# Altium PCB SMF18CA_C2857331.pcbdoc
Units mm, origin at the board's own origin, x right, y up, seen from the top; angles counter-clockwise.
Board outline 17.27 x 14.65 mm, 2 copper layers (Top Layer, Bottom Layer), stack 0 mm thick; 1 components, 0 nets, 2 pads, 0 vias.
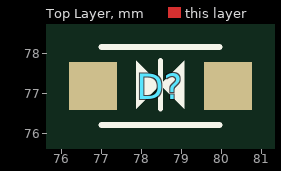
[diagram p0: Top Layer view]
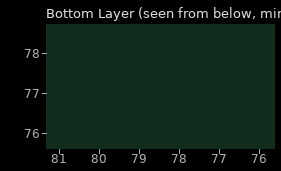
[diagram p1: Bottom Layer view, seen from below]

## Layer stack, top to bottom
Top Layer: signal copper (thickness not stored)
Bottom Layer: signal copper (thickness not stored)

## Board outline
87.12,69.85 69.85,69.85 69.85,84.502 87.12,84.502

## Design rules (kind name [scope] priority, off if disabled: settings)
PasteMaskExpansion "Paste Mask Expansion" [All] p1: expansion=0
SolderMaskExpansion "Solder Mask Expansion" [IsVia] p1: expansion=-25.4 istentingtop=TRUE
SolderMaskExpansion "Solder Mask Expansion" [All] p2: expansion=0.051 istentingtop=FALSE

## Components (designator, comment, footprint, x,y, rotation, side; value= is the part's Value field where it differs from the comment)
D? "SMF18CA" SMF_L2.8-W1.8-LS3.7-BI 78.485,77.176 r0 top

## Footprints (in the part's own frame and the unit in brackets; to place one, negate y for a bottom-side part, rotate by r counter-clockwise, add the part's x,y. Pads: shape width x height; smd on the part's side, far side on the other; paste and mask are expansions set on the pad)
SMF_L2.8-W1.8-LS3.7-BI [mm]
  rect 1.2x1.2 smd: 1(-1.685,0) 2(1.685,0)
  silkscreen extent -1.48,-0.98 1.48,0.98

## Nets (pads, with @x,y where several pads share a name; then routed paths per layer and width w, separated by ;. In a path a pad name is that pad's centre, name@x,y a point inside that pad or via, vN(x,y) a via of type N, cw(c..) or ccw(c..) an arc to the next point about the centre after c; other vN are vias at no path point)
pads on no net: D?.1 D?.2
